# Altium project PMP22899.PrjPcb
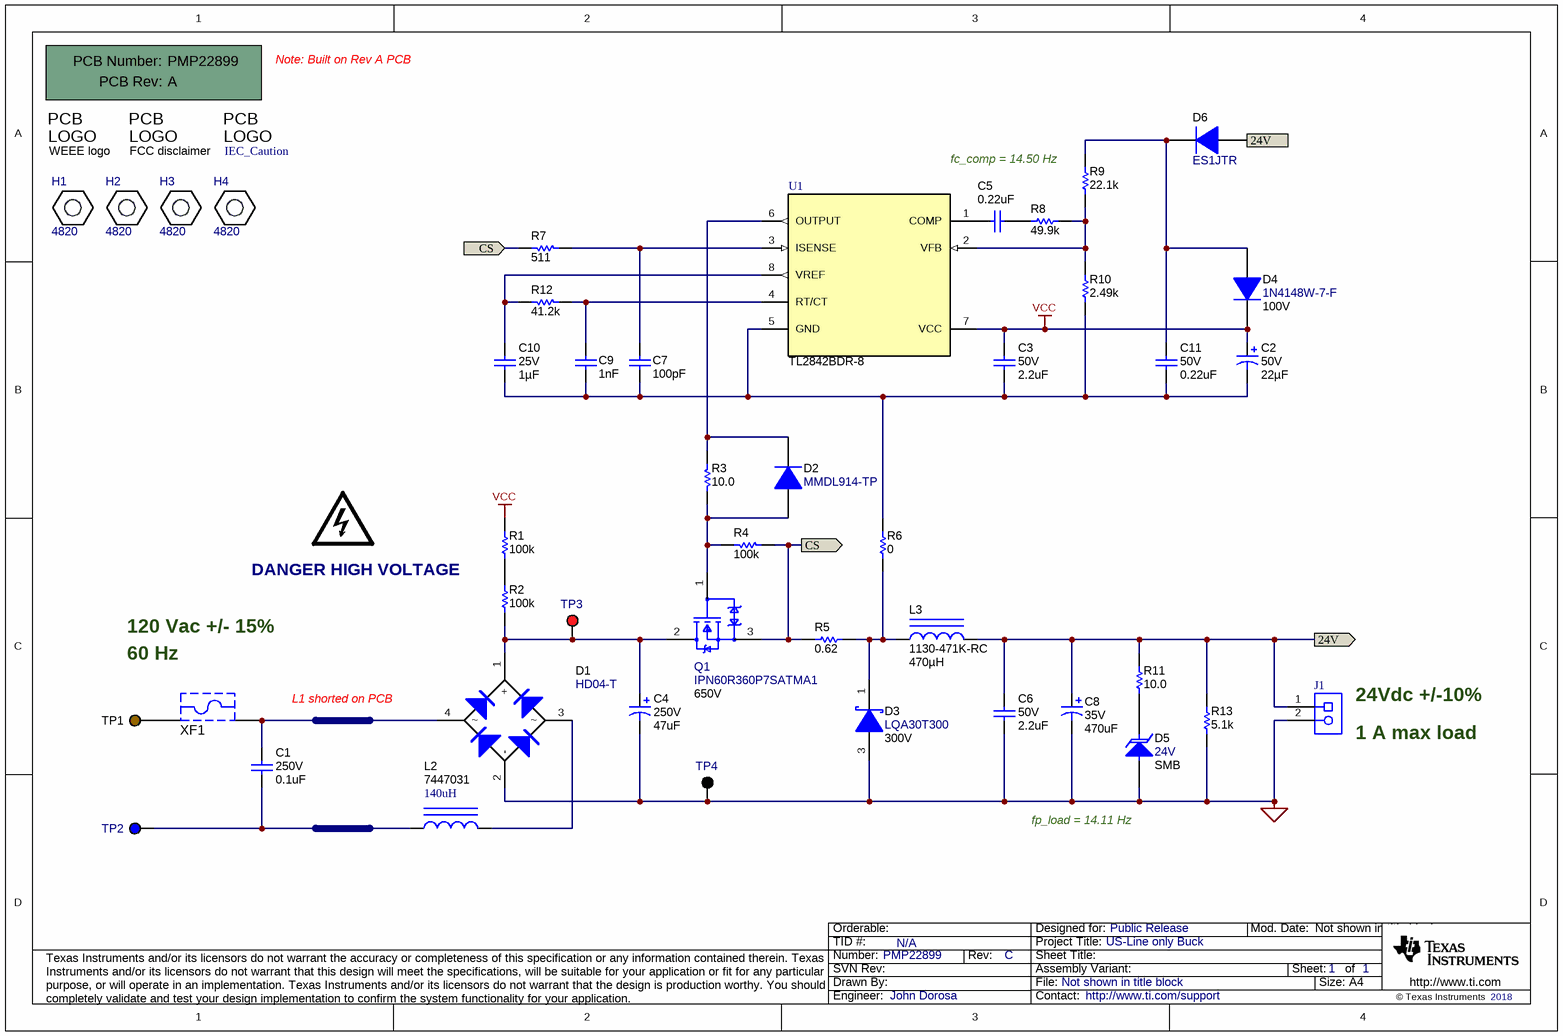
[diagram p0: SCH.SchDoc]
TID: N/A; TechSupport: http://www.ti.com/support; SCH_Rev: C; PRJ_Title: US-Line only Buck; PRJ_Number: PMP22899; PRJ_Engineer: John Dorosa; PRJ_Customer: Public Release; PCB_Rev: A; PCB_Layout: John Dorosa; CopyrightYear: 2018
1 sheet, 49 parts. Net scope: flat (ports and power ports of the same name join across sheets).
Board file: PCB.PcbDoc

## Sheet SCH.SchDoc
size A4; Date: Not shown in title block; ApprovedBy: Not shown in title block; CheckedBy: Not shown in title block; Author: Not shown in title block; CompanyName: Not shown in title block; Engineer: Not shown in title block; Organization: Not shown in title block; Address1: Not shown in title block; Address2: Not shown in title block; Address3: Not shown in title block; Address4: Not shown in title block; DocumentNumber: 1; Revision: Use project parameter SCH_Rev; SheetNumber: 1; SheetTotal: 1; PageSetup: Record=PageOptions¦CenterHorizontal=True¦CenterVertical=True¦PrintScale=1.00¦XCorrection=1.00¦YCorrection=1.00¦PrintKind=0¦BorderSize=5000000¦LeftOffset=0¦BottomOffset=0¦Orientation=2¦PaperLength=1000¦PaperWidth=1000¦Scale=100¦PaperSource=15¦PrintQuality=600¦MediaType=1¦DitherType=10¦PaperKind=Letter¦PrintScaleMode=1

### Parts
!PCB1  Printed Circuit Board  (value not drawn)  (mechanical)
C1  VDC_V: 250V  ValueDisplayed: 0.1uF  [B32529_450x950x730]  (hidden comment: B32529C3104K)
C2  VDC_V: 50V  ValueDisplayed: 22µF  [UKL_630x1100]  (hidden comment: UKL1H220KEDANA)
C3  VDC_V: 50V  ValueDisplayed: 2.2uF  [1206_180]  (hidden comment: GRM31CR71H225KA88L)
C4  VDC_V: 250V  ValueDisplayed: 47uF  [CAPPR7.5-16x20]  (hidden comment: EEUED2E470S)
C5  ValueDisplayed: 0.22uF  [0603L]  (hidden comment: GRM188R71E224KA88D)
C6  VDC_V: 50V  ValueDisplayed: 2.2uF  [1206_180]  (hidden comment: GRM31CR71H225KA88L)
C7  ValueDisplayed: 100pF  [0402]  (hidden comment: GRM1555C1H101JA01D)
C8  VDC_V: 35V  ValueDisplayed: 470uF  [HW_1000x1600]  (hidden comment: UHW1V471MPD)
C9  Cap_F: 1nF  [0603L]  (hidden comment: GRM188R71E102KA01D)
C10  VDC_V: 25V  Cap_F: 1µF  [0603L]  (hidden comment: GRM188R71E105KA12D)
C11  VDC_V: 50V  ValueDisplayed: 0.22uF  [0603]  (hidden comment: GRM188R71H224KAC4D)
D1  HD04-T  [MiniDIP]
D2  MMDL914-TP  [SOD-323]
D3  LQA30T300  value 300V  [TO-220AC]
D4  1N4148W-7-F  value 100V  [SOD-123]
D5  value 24V  [SMB]  (hidden comment: SMBJ24A-13-F)
D6  ES1JTR  [SMA]
H1  4820  [KEYSTONE_4820]
H2  4820  [KEYSTONE_4820]
H3  4820  [KEYSTONE_4820]
H4  4820  [KEYSTONE_4820]
J1  691214110002  [Wurth_691214110002]  (value not drawn)
L2  7447031  ValueDisplayed: 140uH  [WE-FI_1350x700]
L3  1130-471K-RC  ValueDisplayed: 470µH  [1130-471K]
LOGO1  DANGER HIGH VOLTAGE  [IEC_HighVoltage_Small]  (no BOM)
Logo2  WEEE logo  [WEEE_Minimum]  (no BOM)
Logo3  FCC disclaimer  [FCC_disclaimer]  (no BOM)
Logo4  Lib Reference: IEC_Caution  [IEC_Caution_Small]  (hidden comment: CAUTION.  READ USER GUIDE BEFORE USE)  (no BOM)
Q1  IPN60R360P7SATMA1  VdsMax_V: 650V  [FP-IPN60R360P7SATMA1_SOT223-MFG]
R1  ValueDisplayed: 100k  [2512]  (hidden comment: CRCW2512100KJNEG)
R2  ValueDisplayed: 100k  [2512]  (hidden comment: CRCW2512100KJNEG)
R3  ValueDisplayed: 10.0  [0603]  (hidden comment: CRCW060310R0FKEA)
R4  ValueDisplayed: 100k  [0603]  (hidden comment: CRCW0603100KFKEA)
R5  ValueDisplayed: 0.62  [1206]  (hidden comment: CSR1206FTR620)
R6  ValueDisplayed: 0  [1206L]  (hidden comment: CRCW12060000Z0EA)
R7  ValueDisplayed: 511  [0402]  (hidden comment: CRCW0402511RFKED)
R8  ValueDisplayed: 49.9k  [0402]  (hidden comment: CRCW040249K9FKED)
R9  ValueDisplayed: 22.1k  [0402]  (hidden comment: CRCW040222K1FKED)
R10  ValueDisplayed: 2.49k  [0402]  (hidden comment: CRCW04022K49FKED)
R11  ValueDisplayed: 10.0  [1206]  (hidden comment: Resistor)
R12  ValueDisplayed: 41.2k  [0402]  (hidden comment: CRCW040241K2FKED)
R13  ValueDisplayed: 5.1k  [1206]  (hidden comment: Resistor)
TP1  5125  [Keystone5125]  (value not drawn)
TP2  5127  [Keystone5127]  (value not drawn)
TP3  5000  [Keystone5000]  (value not drawn)
TP4  5001  [Keystone5001]  (value not drawn)
U1  TL2842BDR-8  [D0008A_N]
XF1  56000001009  [FuseHolder_560000010]  (value not drawn)

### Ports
24V (in), 24V (out), CS (in), CS (out)

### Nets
GND: C4.2(-) C6.2 C8.2(-) D1.2(-) D3.3(K) D5.2(A) J1.2 R13.1 TP4.1
VCC: C2.1(+) C3.1 D4.1(K) R1.2 U1.7(VCC)
24V: C6.1 C8.1(+) D6.2(A) J1.1 L3.2 R11.2 R13.2 ; port 24V
CS: Q1.3(Source) R4.2 R5.1 R7.1 ; port CS
NetC1_1: C1.1 D1.4 XF1.2
NetC1_2: C1.2 L2.1 TP2.1
NetC2_2: C2.2(-) C3.2 C7.1 C9.2 C10.2 C11.2 R6.2 R10.1 U1.5(GND)
NetC4_1: C4.1(+) D1.1(+) Q1.2(Drain) R2.1 TP3.1
NetC5_1: C5.1 U1.1(COMP)
NetC5_2: C5.2 R8.1
NetC7_2: C7.2 R7.2 U1.3(ISENSE)
NetC9_1: C9.1 R12.1 U1.4(RT/CT)
NetC10_1: C10.1 R12.2 U1.8(VREF)
NetC11_1: C11.1 D4.2(A) D6.1(K) R9.2
NetD1_3: D1.3 L2.2
NetD2_1: D2.1(K) R3.2 U1.6(OUTPUT)
NetD2_2: D2.2(A) Q1.1(Gate) R3.1 R4.1
NetD3_1: D3.1(A) L3.1 R5.2 R6.1
NetD5_1: D5.1(K) R11.1
NetR1_1: R1.1 R2.2
NetR8_2: R8.2 R9.1 R10.2 U1.2(VFB)
NetTP1_1: TP1.1 XF1.1

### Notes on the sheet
- Note: Built on Rev A PCB
- (near R9) fc_comp = 14.50 Hz
- 120 Vac +/- 15%
- 60 Hz
- L1 shorted on PCB
- (near J1) 24Vdc +/-10%
- (near J1) 1 A max load
- fp_load = 14.11 Hz

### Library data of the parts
!PCB1 = CMP-0003618-2: Manufacturer: Any; PartNumber: PMP22899
C1 = CMP-0012332-3: CAP, Film, 0.1 uF, 250 V, +/- 10%, TH; Manufacturer: TDK; TaMin_C: -55°C; Polarized: N; SizeAreaWB_mm2: 60.45; Value1: Unknown; Value: 0.1uF; TaMax_C: 125°C; SizeZ_mm: 9.5; SizeX_mm: 7.3; SizeY_mm: 4.5; Cap_Case: 4.5x9.5x7.3mm; SizeArea_mm2: 32.85; Cap_F: 100nF; AEC Category: Q200
C2 = CMP-0080730-1: CAP, AL, 22 µF, 50 V, +/- 10%, TH; Manufacturer: Nichicon; SizeAreaWB_mm2: 68.89; SizeArea_mm2: 39.69; AEC Qualified: N; AEC Category: Q200; Value: 22uF; TaMax_C: 105°C; SizeZ_mm: 12; Polarized: Y; TaMin_C: -40°C; SizeY_mm: 6.3; U/M: EA; CompType: Capacitor; Cap_Case: 6.3x11mm
C3 C6 = CMP-0008968-2: CAP, CERM, 2.2 uF, 50 V, +/- 10%, X7R, 1206; Manufacturer: MuRata; TaMin_C: -55°C; Polarized: N; SizeAreaWB_mm2: 10.92; Value1: Unknown; U/M: EA; Value: 2.2uF; TaMax_C: 125°C; SizeZ_mm: 1.8; SizeX_mm: 3.2; SizeY_mm: 1.6; Cap_Case: 1206; SizeArea_mm2: 5.12; Cap_F: 2.2µF; AEC Category: Q200
C4 = CMP-0010021-3: CAP, AL, 47 uF, 250 V, +/- 20%, 0.380955 ohm, TH; Manufacturer: Panasonic; TaMin_C: -25°C; Polarized: Y; SizeAreaWB_mm2: 324; U/M: EA; Value: 47uF; TaMax_C: 105°C; SizeZ_mm: 20; SizeX_mm: 16; AC_Derating: 0.3; SizeArea_mm2: 256; CompType: Capacitor; Cap_F: 47µF; IRMS_A: 990mA; AEC Category: Q200
C5 = CMP-0007415-4: CAP, CERM, 0.22 uF, 25 V, +/- 10%, X7R, 0603; Manufacturer: MuRata; TaMin_C: -55°C; Polarized: N; SizeAreaWB_mm2: 4.68; Value1: Unknown; U/M: EA; Value: 0.22uF; TaMax_C: 125°C; SizeZ_mm: 1; SizeX_mm: 1.6; SizeY_mm: 0.8; Cap_Case: 0603; Value2: 25V; SizeArea_mm2: 1.28; Cap_F: 220nF; AEC Category: Q200
C7 = CMP-0006410-2: CAP, CERM, 100 pF, 50 V, +/- 5%, C0G/NP0, 0402; Manufacturer: MuRata; TaMin_C: -55°C; Polarized: N; SizeAreaWB_mm2: 3; Value1: Unknown; U/M: EA; Value: 100pF; TaMax_C: 125°C; SizeZ_mm: 0.6; SizeX_mm: 1; SizeY_mm: 0.5; Value2: 50V; AEC Category: Q200
C8 = CMP-0010541-2: CAP, AL, 470 uF, 35 V, +/- 20%, 0.03 ohm, TH; Manufacturer: Nichicon; TaMin_C: -40°C; ESR_ohm: 0.03; Polarized: Y; SizeAreaWB_mm2: 144; U/M: EA; Value: 470uF; TaMax_C: 105°C; SizeZ_mm: 17.5; SizeX_mm: 10; Cap_Case: 10x16mm; SizeArea_mm2: 100; CompType: Capacitor; AEC Qualified: N; Cap_F: 470µF; IRMS_A: 2A; AEC Category: Q200
C9 = CMP-0007402-5: CAP, CERM, 1000 pF, 25 V, +/- 10%, X7R, 0603; Manufacturer: MuRata; Value1: Unknown; VDC_V: 25V; TaMax_C: 125°C; Polarized: N; SizeArea_mm2: 1.28; Cap_Case: 0603; AEC Category: Q200; Value: 1000pF; TaMin_C: -55°C; SizeX_mm: 1.6; U/M: EA; MFG_Status: TI_Obsolete; SizeZ_mm: 1; SizeAreaWB_mm2: 4.68; SizeY_mm: 0.8
C10 = CMP-0007405-5: CAP, CERM, 1 uF, 25 V, +/- 10%, X7R, 0603; Manufacturer: MuRata; Cap_Case: 0603; AEC Category: Q200; Value: 1uF; SizeX_mm: 1.6; U/M: EA; Value1: Unknown; SizeAreaWB_mm2: 4.68; SizeY_mm: 0.8; TaMin_C: -55°C; SizeZ_mm: 1; Polarized: N; MFG_Status: TI_Obsolete; TaMax_C: 125°C; SizeArea_mm2: 1.28
C11 = CMP-0007445-4: CAP, CERM, 0.22 uF, 50 V, +/- 10%, X7R, 0603; Manufacturer: MuRata; TaMin_C: -55°C; Polarized: N; SizeAreaWB_mm2: 4.68; Value1: Unknown; U/M: EA; Value: 0.22uF; TaMax_C: 125°C; SizeZ_mm: 1; SizeX_mm: 1.6; SizeY_mm: 0.8; SizeArea_mm2: 1.28; Cap_F: 220nF; AEC Category: Q200
D1 = CMP-0029217-3: Diode, Switching-Bridge, 400 V, 0.8 A, MiniDIP; Manufacturer: Diodes Inc.; SizeZ_mm: 3; Value1: 0.8A; AEC Category: Q101; Vf_V: 1V; Green_REACh: Passed; TJmax_C: 150°C; SizeArea_mm2: 34.3; SizeX_mm: 7; SizeY_mm: 4.9; Vr_V: 400V; Green_Lifecycle: Active; Value: 400V; Io_A: 800mA; SizeAreaWB_mm2: 62.1
D2 = CMP-0029045-2: Diode, Switching, 100 V, 0.2 A, SOD-323; Manufacturer: Micro Commercial Components; Value: 100V; TJmax_C: 150°C; Vf_V: 1V; Value1: 0.2A; SizeArea_mm2: 3.645; SizeZ_mm: 1; Green_Lifecycle: Not Set; SizeY_mm: 1.35; Green_REACh: Incomplete; SizeAreaWB_mm2: 8.695; SizeX_mm: 2.7; Io_A: 200mA; AEC Category: Q101
D3 = CMP-0028844-2: Diode, Schottky, 300 V, 30 A, TH; Manufacturer: Power Integrations; Green_Lifecycle: Not Set; SizeX_mm: 10.15; AEC Category: Q101; Green_REACh: Incomplete; TJmax_C: 150°C; SizeY_mm: 4.5; Io_A: 30A; AEC Qualified: N; Value2: 1.95V; SizeZ_mm: 23; SizeArea_mm2: 45.675; RJC_CperW: 1.1; SizeAreaWB_mm2: 78.975
D4 = CMP-0029001-2: Diode, Ultrafast, 100 V, 0.15 A, SOD-123; Manufacturer: Diodes Inc.; SizeX_mm: 3.85; Value2: 1.25V; Green_REACh: Passed; TJmax_C: 150°C; AEC Category: Q101; SizeAreaWB_mm2: 13.095; Green_Lifecycle: Active; SizeY_mm: 1.7; Value1: 0.15A; SizeArea_mm2: 6.545; Io_A: 150mA; SizeZ_mm: 1.35
D5 = CMP-0005557-4: Diode, TVS, Uni, 24 V, 38.9 Vc, SMB; Manufacturer: Diodes Inc.; Value1: 600W; SizeArea_mm2: 21.336; Vbr_Max: 30.7V; SizeY_mm: 3.81; Vbr_Min: 26.7V; SizeX_mm: 5.6; SizeAreaWB_mm2: 44.156; Vc: 38.9V; SizeZ_mm: 2.6; Ipp: 15.4A; AEC Category: Q101
D6 = CMP-0067545-2: Diode, Superfast Rectifier, 600 V, 1 A, SMA; Manufacturer: SMC Diode Solutions; SizeZ_mm: 2.87; Io_A: 1A; SizeY_mm: 2.92; SizeAreaWB_mm2: 37.3428; Value: 600V; SizeX_mm: 5.59; SizeArea_mm2: 16.3228; Value2: 1.7V; AEC Qualified: N; TJmax_C: 150°C; AEC Category: Q101; RJC_CperW: 35.0
H1-H4 = CMP-0003652-1: Manufacturer: Keystone; CompType: Standoff
J1 = CMP-0054825-2: Terminal Block, 3.5mm, 2x1, Tin, TH; Manufacturer: Wurth Elektronik; Pitch_mm: 3.5; CT: TRUE; CNHeader: FALSE; Voltage_V: 300V; Gender: Female; Cert_UL: Y; Row_Count: 1; Current_A: 10A
L2 = CMP-0064732-2: Inductor, Toroid, Powdered Iron, 140 uH, 1 A, 0.11 ohm, TH; Manufacturer: Wurth Elektronik; Irms: 1A @ 40C rise; Green_Lifecycle: Active; SizeAreaWB_mm2: 139.5; DCR_ohm: 0.11; Green_REACh: Passed; Value: 140uH; Imax_A: 1A; SizeZ_mm: 13.5; SizeX_mm: 7; SizeArea_mm2: 94.5; Ind_H: 140µH; AEC Qualified: N; AEC Category: Q200
L3 = CMP-0074883-1: Inductor, Wirewound, Ferrite, 470 µH, 4 A, 0.187 ohm, TH; Manufacturer: Bourns; Isat: 4A @ 5% inductance drop; Irms: 4A @ 50C rise; SizeAreaWB_mm2: 896.4036; DCR_ohm: 0.187; Value: 470uH; Imax_A: 4A; SizeZ_mm: 21.336; SizeX_mm: 27.94; SizeArea_mm2: 780.6436; AEC Qualified: N; AEC Category: Q200
LOGO1 = CMP-0074835-1: IEC 61010-1 High Voltage Warning; SymbolCreator: a0412235
Logo2 = CMP-0074769-1
Logo3 = CMP-0074847-1: FCC_disclaimer; Library Reference: Logo
Logo4 = CMP-0074836-1: IEC 61010-1 Caution Warning; SymbolCreator: a0412235
Q1 = CMP-0087676-1: MOSFET N-CHANNEL 600V 9A SOT223; Manufacturer: Infineon; QgTyp_nC: 13nC @ 10V; ChMode: False; Vgs_V: 20V; SizeZ_mm: 1.8mm; AEC Qualified: No; Rdson45_ohm: 0.3
R1 R2 = CMP-0015866-3: RES, 100 k, 5%, 1 W, AEC-Q200 Grade 0, 2512; Manufacturer: Vishay-Dale; Power_W: 1W; TempCo: 200 ppm/C; Value: 100k; EIA_Code: E24; SizeX_mm: 6.3; SizeY_mm: 3.2; SizeZ_mm: 0.71; SizeArea_mm2: 20.16; AEC Qualified: Y; VDC_V: 500V; AEC Grade: 0; AEC Category: Q200
R3 = CMP-0022003-4: RES, 10.0, 1%, 0.1 W, AEC-Q200 Grade 0, 0603; Manufacturer: Vishay-Dale; Power_W: 100mW; TempCo: 100 ppm/C; Value_Code: 10R0; Value: 10.0; EIA_Code: E96; Res_ohm: 10; SizeX_mm: 1.6; SizeY_mm: 0.8; SizeZ_mm: 1; Value2: 0.1W; SizeArea_mm2: 1.28; AEC Qualified: Y; VDC_V: 75V; AEC Category: Q200; AEC Grade: 0
R4 = CMP-0021990-4: RES, 100 k, 1%, 0.1 W, AEC-Q200 Grade 0, 0603; Manufacturer: Vishay-Dale; Power_W: 100mW; TempCo: 100 ppm/C; Value: 100k; EIA_Code: E96; SizeX_mm: 1.6; SizeY_mm: 0.8; SizeZ_mm: 1; Value2: 0.1W; SizeArea_mm2: 1.28; AEC Qualified: Y; VDC_V: 75V; AEC Category: Q200; AEC Grade: 0
R5 = CMP-0017274-2: RES, 0.62, 1%, 0.5 W, 1206; Manufacturer: Stackpole Electronics Inc; Power_W: 500mW; TempCo: 100 ppm/C; Value_Code: R620; U/M: EA; Value: 0.62; EIA_Code: E96; SizeX_mm: 3.2; SizeY_mm: 1.6; SizeZ_mm: 1.35; Value2: 0.5W; SizeArea_mm2: 5.12; AEC Qualified: N; AEC Category: Q200
R6 = CMP-0018573-3: RES, 0, 5%, 0.25 W, AEC-Q200 Grade 0, 1206; Manufacturer: Vishay-Dale; Power_W: 250mW; TempCo: 200 ppm/C; Value_Code: 0000; Value: 0; EIA_Code: E24; SizeX_mm: 3.2; SizeY_mm: 1.6; SizeZ_mm: 1.35; Value2: 0.25W; SizeArea_mm2: 5.12; AEC Qualified: Y; VDC_V: 200V; AEC Category: Q200
R7 = CMP-0026436-2: RES, 511, 1%, 0.063 W, AEC-Q200 Grade 0, 0402; Manufacturer: Vishay-Dale; Power_W: 63mW; TempCo: 100 ppm/C; Value_Code: 511R; Value: 511; EIA_Code: E96; SizeX_mm: 1; SizeY_mm: 0.5; SizeZ_mm: 0.6; Value2: 0.063W; AEC Qualified: Y; VDC_V: 50V; AEC Category: Q200; AEC Grade: 0
R8 = CMP-0026403-2: RES, 49.9 k, 1%, 0.063 W, AEC-Q200 Grade 0, 0402; Manufacturer: Vishay-Dale; Power_W: 63mW; TempCo: 100 ppm/C; Value_Code: 49k9; Value: 49.9k; EIA_Code: E96; SizeX_mm: 1; SizeY_mm: 0.5; SizeZ_mm: 0.6; Value2: 0.063W; AEC Qualified: Y; VDC_V: 50V; AEC Category: Q200; AEC Grade: 0
R9 = CMP-0026178-2: RES, 22.1 k, 1%, 0.063 W, AEC-Q200 Grade 0, 0402; Manufacturer: Vishay-Dale; Power_W: 63mW; TempCo: 100 ppm/C; Value_Code: 22k1; Value: 22.1k; EIA_Code: E96; SizeX_mm: 1; SizeY_mm: 0.5; SizeZ_mm: 0.6; Value2: 0.063W; AEC Qualified: Y; VDC_V: 50V; AEC Category: Q200; AEC Grade: 0
R10 = CMP-0026237-2: RES, 2.49 k, 1%, 0.063 W, AEC-Q200 Grade 0, 0402; Manufacturer: Vishay-Dale; Power_W: 63mW; TempCo: 100 ppm/C; Value_Code: 2k49; Value: 2.49k; EIA_Code: E96; SizeX_mm: 1; SizeY_mm: 0.5; SizeZ_mm: 0.6; Value2: 0.063W; AEC Qualified: Y; VDC_V: 50V; AEC Category: Q200; AEC Grade: 0
R11 = CMP-0016583-3: RES, 10.0, 1%, 0.25 W, AEC-Q200 Grade 0, 1206; PartNumber: CRCW120610R0FKEA; Manufacturer: Vishay-Dale; Value: 10.0; Res_ohm: 10; Value_Code: 10R0; Power_W: 250mW; Value2: 0.25W; VDC_V: 200V; TempCo: 100 ppm/C; EIA_Code: E96; AEC Category: Q200; AEC Grade: 0; AEC Qualified: Y; SizeArea_mm2: 5.12; SizeX_mm: 3.2; SizeY_mm: 1.6; SizeZ_mm: 1.35
R12 = CMP-0026371-2: RES, 41.2 k, 1%, 0.063 W, AEC-Q200 Grade 0, 0402; Manufacturer: Vishay-Dale; Power_W: 63mW; TempCo: 100 ppm/C; Value_Code: 41k2; Value: 41.2k; EIA_Code: E96; SizeX_mm: 1; SizeY_mm: 0.5; SizeZ_mm: 0.6; Value2: 0.063W; AEC Qualified: Y; VDC_V: 50V; AEC Category: Q200; AEC Grade: 0
R13 = CMP-0018703-3: RES, 5.1 k, 5%, 0.25 W, AEC-Q200 Grade 0, 1206; PartNumber: CRCW12065K10JNEA; Manufacturer: Vishay-Dale; Value: 5.1k; Value_Code: 5k10; Power_W: 250mW; Value2: 0.25W; VDC_V: 200V; TempCo: 200 ppm/C; EIA_Code: E24; AEC Category: Q200; AEC Grade: 0; AEC Qualified: Y; SizeArea_mm2: 5.12; SizeX_mm: 3.2; SizeY_mm: 1.6; SizeZ_mm: 1.35
TP1 = CMP-0055157-1: Test Point, Multipurpose, Brown, TH; Manufacturer: Keystone; CNHeader: FALSE; Green_Lifecycle: Active; Green_REACh: Passed; ContactFinish: Silver; CT: TRUE
TP2 = CMP-0055156-1: Test Point, Multipurpose, Blue, TH; Manufacturer: Keystone; CNHeader: FALSE; Green_Lifecycle: Active; Green_REACh: Passed; ContactFinish: Silver; CT: TRUE
TP3 = CMP-0055137-1: Test Point, Miniature, Red, TH; Manufacturer: Keystone; CNHeader: FALSE; ContactFinish: Silver; CT: TRUE; Green_Lifecycle: Active; Green_REACh: Passed
TP4 = CMP-0055138-1: Test Point, Miniature, Black, TH; Manufacturer: Keystone; CNHeader: FALSE; ContactFinish: Silver; CT: TRUE; Green_Lifecycle: Active; Green_REACh: Passed
U1 = CMP-0031461-1: High-Performance Current-Mode PWM Controllers with Current control, 100% Duty Cycle, -40 to 85 degC, 8-pin SOIC (D),Green (RoHS & no Sb/Br); Manufacturer: Texas Instruments; Duty Cycle(Max)(%): 100; UVLO Thresholds On/Off(V): 16/10; Frequency(Max)(kHz): 500; Topology: Boost, Flyback, Forward; Rating: Catalog; Regulated Outputs(#): 1
XF1 = CMP-0003627-1: Fuse Holder, TR5, TH; Manufacturer: Littelfuse

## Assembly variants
001: not fitted H1 H2 H3 H4 L1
